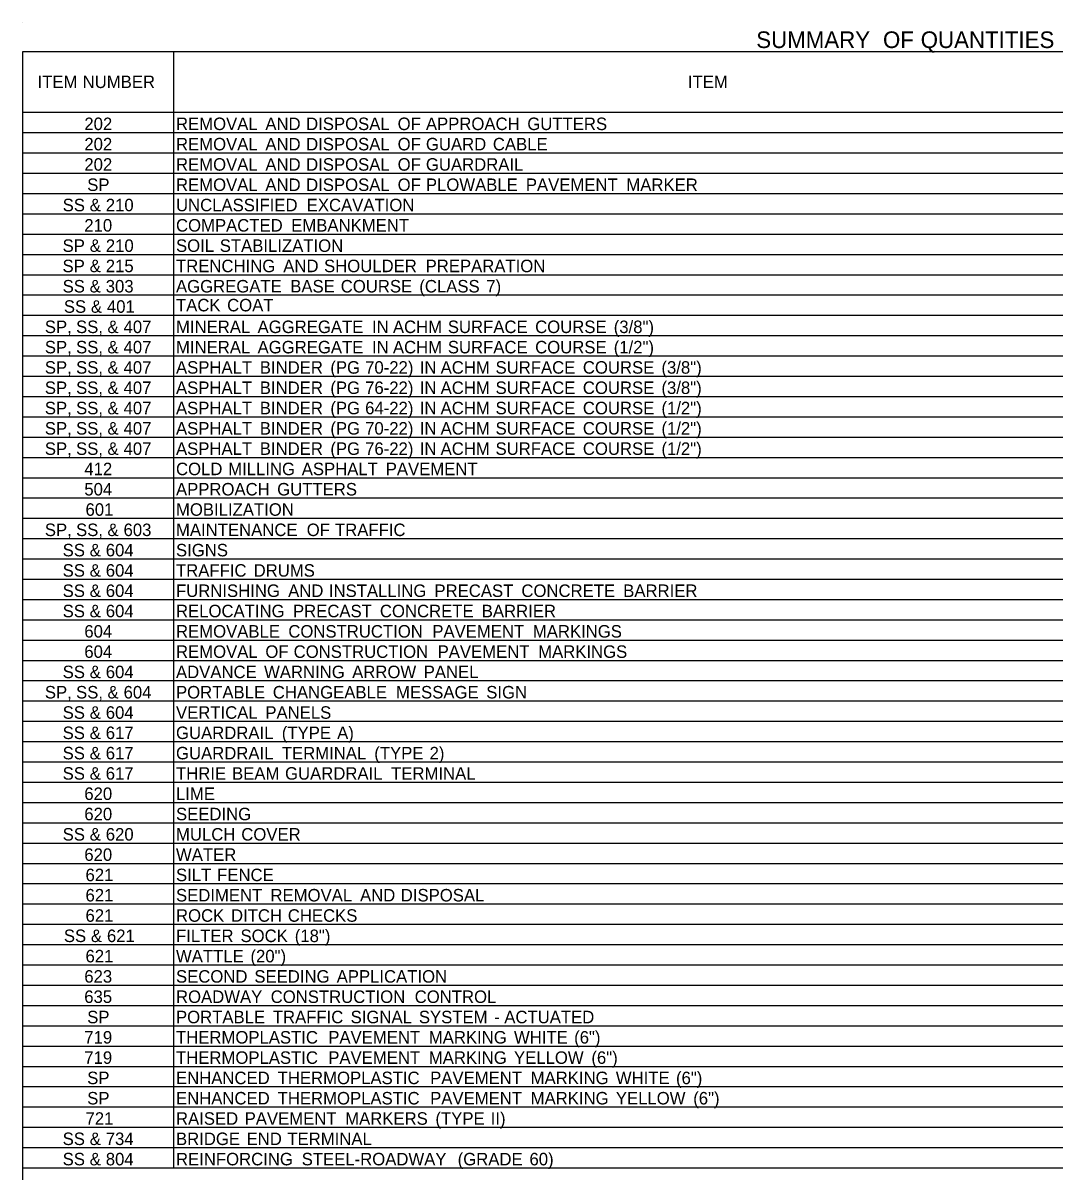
# Model space of a CAD drawing. Extents: x 540541 to 1930787, y -1948574 to 596640.
# Drawn here: x 548276 to 548771, y -1948161 to -1947610 of the extents above; entities that cross this region are included whole.
import ezdxf

# ---------------------------------------------------------------- set-up
doc = ezdxf.new("R2010")
doc.units = 0
doc.layers.add('Default', color=7, linetype='Continuous')
doc.layers.add('R_Border', color=7, linetype='Continuous')

msp = doc.modelspace()

# ---------------------------------------------------------------- linework, layer by layer
at = {"layer": 'Default'}
for p, q in [((548275.56, -1947623.57), (549254.46, -1947623.57)), ((548275.56, -1948315.82), (548275.56, -1947623.57)), ((548348.1, -1948159.82), (548348.1, -1947623.57)), ((548275.56, -1947652.82), (549254.46, -1947652.82)), ((548275.56, -1947652.82), (549254.46, -1947652.82)), ((548348.1, -1948159.82), (548348.1, -1947652.82)), ((548275.56, -1947662.57), (549254.46, -1947662.57)), ((548275.56, -1947672.32), (549254.46, -1947672.32)), ((548275.56, -1947682.07), (549254.46, -1947682.07)), ((548275.56, -1947691.82), (549254.46, -1947691.82)), ((548275.56, -1947701.57), (549254.46, -1947701.57)), ((548275.56, -1947711.32), (549254.46, -1947711.32)), ((548275.56, -1947721.07), (549254.46, -1947721.07)), ((548275.56, -1947730.82), (549254.46, -1947730.82)), ((548275.56, -1947740.57), (549254.46, -1947740.57)), ((548275.56, -1947750.32), (549254.46, -1947750.32)), ((548275.56, -1947760.07), (549254.46, -1947760.07)), ((548275.56, -1947769.82), (549254.46, -1947769.82)), ((548275.56, -1947779.57), (549254.46, -1947779.57)), ((548275.56, -1947789.32), (549254.46, -1947789.32)), ((548275.56, -1947799.07), (549254.46, -1947799.07)), ((548275.56, -1947808.82), (549254.46, -1947808.82)), ((548275.56, -1947818.57), (549254.46, -1947818.57)), ((548275.56, -1947828.32), (549254.46, -1947828.32)), ((548275.56, -1947838.07), (549254.46, -1947838.07)), ((548275.56, -1947847.82), (549254.46, -1947847.82)), ((548275.56, -1947857.57), (549254.46, -1947857.57)), ((548275.56, -1947867.32), (549254.46, -1947867.32)), ((548275.56, -1947877.07), (549254.46, -1947877.07)), ((548275.56, -1947886.82), (549254.46, -1947886.82)), ((548275.56, -1947896.57), (549254.46, -1947896.57)), ((548275.56, -1947906.32), (549254.46, -1947906.32)), ((548275.56, -1947916.07), (549254.46, -1947916.07)), ((548275.56, -1947925.82), (549254.46, -1947925.82)), ((548275.56, -1947935.57), (549254.46, -1947935.57)), ((548275.56, -1947945.32), (549254.46, -1947945.32)), ((548275.56, -1947955.07), (549254.46, -1947955.07)), ((548275.56, -1947964.82), (549254.46, -1947964.82)), ((548275.56, -1947974.57), (549254.46, -1947974.57)), ((548275.56, -1947984.32), (549254.46, -1947984.32)), ((548275.56, -1947994.07), (549254.46, -1947994.07)), ((548275.56, -1948003.82), (549254.46, -1948003.82)), ((548275.56, -1948013.57), (549254.46, -1948013.57)), ((548275.56, -1948023.32), (549254.46, -1948023.32)), ((548275.56, -1948033.07), (549254.46, -1948033.07)), ((548275.56, -1948042.82), (549254.46, -1948042.82)), ((548275.56, -1948052.57), (549254.46, -1948052.57)), ((548275.56, -1948062.32), (549254.46, -1948062.32)), ((548275.56, -1948072.07), (549254.46, -1948072.07)), ((548275.56, -1948081.82), (549254.46, -1948081.82)), ((548275.56, -1948091.57), (549254.46, -1948091.57)), ((548275.56, -1948101.32), (549254.46, -1948101.32)), ((548275.56, -1948111.07), (549254.46, -1948111.07)), ((548275.56, -1948120.82), (549254.46, -1948120.82)), ((548275.56, -1948130.57), (549254.46, -1948130.57)), ((548275.56, -1948140.32), (549254.46, -1948140.32)), ((548275.56, -1948150.07), (549254.46, -1948150.07)), ((548275.56, -1948159.82), (549254.46, -1948159.82)), ((548275.56, -1948159.82), (549254.46, -1948159.82))]:
    msp.add_line(p, q, dxfattribs=at)
at = {"layer": 'R_Border'}
msp.add_line((548275.56, -1947609.92), (548275.56, -1947609.92), dxfattribs=at)

# ---------------------------------------------------------------- texts
at = {"layer": 'Default'}
for s, height, p in [(' SUMMARY', 8, (548624.87, -1947621.97)), (' OF', 8, (548685.75, -1947621.97)), (' QUANTITIES', 8, (548703.86, -1947621.97)), ('ITEM', 6, (548282.58, -1947641.19)), (' NUMBER', 6, (548302, -1947641.19)), ('ITEM', 6, (548595.01, -1947641.19)), ('202', 6, (548305.06, -1947661.37)), ('REMOVAL', 6, (548349.08, -1947661.37)), (' AND', 6, (548389.78, -1947661.37)), (' DISPOSAL', 6, (548409.36, -1947661.37)), (' OF', 6, (548453.33, -1947661.37)), (' APPROACH', 6, (548466.91, -1947661.37)), (' GUTTERS', 6, (548515.62, -1947661.37)), ('202', 6, (548305.06, -1947671.12)), ('REMOVAL', 6, (548349.08, -1947671.12)), (' AND', 6, (548389.78, -1947671.12)), (' DISPOSAL', 6, (548409.36, -1947671.12)), (' OF', 6, (548453.33, -1947671.12)), (' GUARD', 6, (548466.91, -1947671.12)), (' CABLE', 6, (548499.07, -1947671.12)), ('202', 6, (548305.06, -1947680.87)), ('REMOVAL', 6, (548349.08, -1947680.87)), (' AND', 6, (548389.78, -1947680.87)), (' DISPOSAL', 6, (548409.36, -1947680.87)), (' OF', 6, (548453.33, -1947680.87)), (' GUARDRAIL', 6, (548466.91, -1947680.87)), ('SP', 6, (548306.42, -1947690.62)), ('REMOVAL', 6, (548349.08, -1947690.62)), (' AND', 6, (548389.78, -1947690.62)), (' DISPOSAL', 6, (548409.36, -1947690.62)), (' OF', 6, (548453.33, -1947690.62)), (' PLOWABLE', 6, (548466.91, -1947690.62)), (' PAVEMENT', 6, (548514.92, -1947690.62)), (' MARKER', 6, (548563.2, -1947690.62)), ('SS', 6, (548294.64, -1947700.37)), (' &', 6, (548305.39, -1947700.37)), (' 210', 6, (548313.12, -1947700.37)), ('UNCLASSIFIED', 6, (548349.08, -1947700.37)), (' EXCAVATION', 6, (548409.66, -1947700.37)), ('210', 6, (548305.04, -1947710.12)), ('COMPACTED', 6, (548349.08, -1947710.12)), (' EMBANKMENT', 6, (548402.2, -1947710.12)), ('SP', 6, (548294.6, -1947719.87)), (' &', 6, (548305.42, -1947719.87)), (' 210', 6, (548313.15, -1947719.87)), ('SOIL', 6, (548349.08, -1947719.87)), (' STABILIZATION', 6, (548367.88, -1947719.87)), ('SP', 6, (548294.57, -1947729.62)), (' &', 6, (548305.39, -1947729.62)), (' 215', 6, (548313.12, -1947729.62)), ('TRENCHING', 6, (548349.08, -1947729.62)), (' AND', 6, (548398.39, -1947729.62)), (' SHOULDER', 6, (548417.97, -1947729.62)), (' PREPARATION', 6, (548466.77, -1947729.62)), (' (CLASS', 6, (548463.74, -1947739.37)), (' 7)', 6, (548495.92, -1947739.37)), ('SS', 6, (548294.63, -1947739.37)), (' &', 6, (548305.38, -1947739.37)), (' 303', 6, (548313.1, -1947739.37)), ('AGGREGATE', 6, (548349.08, -1947739.37)), (' BASE', 6, (548401.74, -1947739.37)), (' COURSE', 6, (548425.99, -1947739.37)), ('SS', 6, (548295.21, -1947749.12)), (' &', 6, (548305.96, -1947749.12)), (' 401', 6, (548313.68, -1947749.12)), ('TACK', 6, (548349.08, -1947748.44)), (' COAT', 6, (548371.42, -1947748.44)), ('SP,', 6, (548286.07, -1947758.87)), (' SS,', 6, (548298.84, -1947758.87)), (' &', 6, (548313.93, -1947758.87)), (' 407', 6, (548321.66, -1947758.87)), ('MINERAL', 6, (548349.08, -1947758.87)), (' AGGREGATE', 6, (548386.04, -1947758.87)), (' IN', 6, (548441.04, -1947758.87)), (' ACHM', 6, (548451.06, -1947758.87)), (' SURFACE', 6, (548477.44, -1947758.87)), (' COURSE', 6, (548519.39, -1947758.87)), (' (3/8")', 6, (548557.14, -1947758.87)), ('SP,', 6, (548286.07, -1947768.62)), (' SS,', 6, (548298.84, -1947768.62)), (' &', 6, (548313.93, -1947768.62)), (' 407', 6, (548321.66, -1947768.62)), ('MINERAL', 6, (548349.08, -1947768.62)), (' AGGREGATE', 6, (548386.04, -1947768.62)), (' IN', 6, (548441.04, -1947768.62)), (' ACHM', 6, (548451.06, -1947768.62)), (' SURFACE', 6, (548477.44, -1947768.62)), (' COURSE', 6, (548519.39, -1947768.62)), (' (1/2")', 6, (548557.14, -1947768.62)), ('SP,', 6, (548286.07, -1947778.37)), (' SS,', 6, (548298.84, -1947778.37)), (' &', 6, (548313.93, -1947778.37)), (' 407', 6, (548321.66, -1947778.37)), ('ASPHALT', 6, (548349.08, -1947778.37)), (' BINDER', 6, (548387.11, -1947778.37)), (' (PG', 6, (548421.01, -1947778.37)), (' 70-22)', 6, (548437.71, -1947778.37)), (' IN', 6, (548463.96, -1947778.37)), (' ACHM', 6, (548473.98, -1947778.37)), (' SURFACE', 6, (548500.36, -1947778.37)), (' COURSE', 6, (548542.31, -1947778.37)), (' (3/8")', 6, (548580.06, -1947778.37)), ('SP,', 6, (548286.07, -1947788.12)), (' SS,', 6, (548298.84, -1947788.12)), (' &', 6, (548313.93, -1947788.12)), (' 407', 6, (548321.66, -1947788.12)), ('ASPHALT', 6, (548349.08, -1947788.12)), (' BINDER', 6, (548387.11, -1947788.12)), (' (PG', 6, (548421.01, -1947788.12)), (' 76-22)', 6, (548437.71, -1947788.12)), (' IN', 6, (548463.96, -1947788.12)), (' ACHM', 6, (548473.98, -1947788.12)), (' SURFACE', 6, (548500.36, -1947788.12)), (' COURSE', 6, (548542.31, -1947788.12)), (' (3/8")', 6, (548580.06, -1947788.12)), ('SP,', 6, (548286.07, -1947797.87)), (' SS,', 6, (548298.84, -1947797.87)), (' &', 6, (548313.93, -1947797.87)), (' 407', 6, (548321.66, -1947797.87)), ('ASPHALT', 6, (548349.08, -1947797.87)), (' BINDER', 6, (548387.11, -1947797.87)), (' (PG', 6, (548421.01, -1947797.87)), (' 64-22)', 6, (548437.71, -1947797.87)), (' IN', 6, (548463.96, -1947797.87)), (' ACHM', 6, (548473.98, -1947797.87)), (' SURFACE', 6, (548500.36, -1947797.87)), (' COURSE', 6, (548542.31, -1947797.87)), (' (1/2")', 6, (548580.06, -1947797.87)), ('SP,', 6, (548286.07, -1947807.62)), (' SS,', 6, (548298.84, -1947807.62)), (' &', 6, (548313.93, -1947807.62)), (' 407', 6, (548321.66, -1947807.62)), ('ASPHALT', 6, (548349.08, -1947807.62)), (' BINDER', 6, (548387.11, -1947807.62)), (' (PG', 6, (548421.01, -1947807.62)), (' 70-22)', 6, (548437.71, -1947807.62)), (' IN', 6, (548463.96, -1947807.62)), (' ACHM', 6, (548473.98, -1947807.62)), (' SURFACE', 6, (548500.36, -1947807.62)), (' COURSE', 6, (548542.31, -1947807.62)), (' (1/2")', 6, (548580.06, -1947807.62)), ('SP,', 6, (548286.07, -1947817.37)), (' SS,', 6, (548298.84, -1947817.37)), (' &', 6, (548313.93, -1947817.37)), (' 407', 6, (548321.66, -1947817.37)), ('ASPHALT', 6, (548349.08, -1947817.37)), (' BINDER', 6, (548387.11, -1947817.37)), (' (PG', 6, (548421.01, -1947817.37)), (' 76-22)', 6, (548437.71, -1947817.37)), (' IN', 6, (548463.96, -1947817.37)), (' ACHM', 6, (548473.98, -1947817.37)), (' SURFACE', 6, (548500.36, -1947817.37)), (' COURSE', 6, (548542.31, -1947817.37)), (' (1/2")', 6, (548580.06, -1947817.37)), ('412', 6, (548305.06, -1947827.12)), ('COLD', 6, (548349.08, -1947827.12)), (' MILLING', 6, (548371.92, -1947827.12)), (' ASPHALT', 6, (548407.26, -1947827.12)), (' PAVEMENT', 6, (548447.62, -1947827.12)), ('504', 6, (548305.04, -1947836.87)), ('APPROACH', 6, (548349.08, -1947836.87)), (' GUTTERS', 6, (548395.46, -1947836.87)), ('601', 6, (548305.61, -1947846.62)), ('MOBILIZATION', 6, (548349.08, -1947846.62)), ('SP,', 6, (548286.07, -1947856.37)), (' SS,', 6, (548298.84, -1947856.37)), (' &', 6, (548313.93, -1947856.37)), (' 603', 6, (548321.66, -1947856.37)), ('MAINTENANCE', 6, (548349.08, -1947856.37)), (' OF', 6, (548409.65, -1947856.37)), (' TRAFFIC', 6, (548423.24, -1947856.37)), ('SS', 6, (548294.64, -1947866.12)), (' 604', 6, (548313.12, -1947866.12)), ('SIGNS', 6, (548349.08, -1947866.12)), (' &', 6, (548305.39, -1947866.12)), ('SS', 6, (548294.64, -1947875.87)), (' &', 6, (548305.39, -1947875.87)), (' 604', 6, (548313.12, -1947875.87)), ('TRAFFIC', 6, (548349.08, -1947875.87)), (' DRUMS', 6, (548384.14, -1947875.87)), ('SS', 6, (548294.64, -1947885.62)), (' &', 6, (548305.39, -1947885.62)), (' 604', 6, (548313.12, -1947885.62)), ('FURNISHING', 6, (548349.08, -1947885.62)), (' AND', 6, (548400.72, -1947885.62)), (' INSTALLING', 6, (548420.3, -1947885.62)), (' PRECAST', 6, (548471.01, -1947885.62)), (' CONCRETE', 6, (548512.78, -1947885.62)), (' BARRIER', 6, (548561.7, -1947885.62)), ('SS', 6, (548294.64, -1947895.37)), (' &', 6, (548305.39, -1947895.37)), (' 604', 6, (548313.12, -1947895.37)), ('RELOCATING', 6, (548349.08, -1947895.37)), (' PRECAST', 6, (548403.05, -1947895.37)), (' CONCRETE', 6, (548444.81, -1947895.37)), (' BARRIER', 6, (548493.74, -1947895.37)), ('604', 6, (548305.04, -1947905.12)), ('REMOVABLE', 6, (548349.08, -1947905.12)), (' CONSTRUCTION', 6, (548400.81, -1947905.12)), (' PAVEMENT', 6, (548469.99, -1947905.12)), (' MARKINGS', 6, (548518.27, -1947905.12)), ('604', 6, (548305.04, -1947914.87)), ('REMOVAL', 6, (548349.08, -1947914.87)), (' OF', 6, (548389.78, -1947914.87)), (' CONSTRUCTION', 6, (548403.36, -1947914.87)), (' PAVEMENT', 6, (548472.54, -1947914.87)), (' MARKINGS', 6, (548520.83, -1947914.87)), ('SS', 6, (548294.64, -1947924.62)), (' &', 6, (548305.39, -1947924.62)), (' 604', 6, (548313.12, -1947924.62)), ('ADVANCE', 6, (548349.08, -1947924.62)), (' WARNING', 6, (548389.16, -1947924.62)), (' ARROW', 6, (548431.48, -1947924.62)), (' PANEL', 6, (548465.85, -1947924.62)), ('SP,', 6, (548286.08, -1947934.37)), (' SS,', 6, (548298.85, -1947934.37)), (' &', 6, (548313.95, -1947934.37)), (' 604', 6, (548321.68, -1947934.37)), ('PORTABLE', 6, (548349.08, -1947934.37)), (' CHANGEABLE', 6, (548393.36, -1947934.37)), (' MESSAGE', 6, (548452.55, -1947934.37)), (' SIGN', 6, (548495.9, -1947934.37)), ('SS', 6, (548294.64, -1947944.12)), (' &', 6, (548305.39, -1947944.12)), (' 604', 6, (548313.12, -1947944.12)), ('VERTICAL', 6, (548349.08, -1947944.12)), (' PANELS', 6, (548389.78, -1947944.12)), ('SS', 6, (548294.63, -1947953.87)), (' &', 6, (548305.38, -1947953.87)), (' 617', 6, (548313.1, -1947953.87)), ('GUARDRAIL', 6, (548349.08, -1947953.87)), (' (TYPE', 6, (548397.69, -1947953.87)), (' A)', 6, (548424.26, -1947953.87)), ('SS', 6, (548294.63, -1947963.62)), (' &', 6, (548305.38, -1947963.62)), (' 617', 6, (548313.1, -1947963.62)), ('GUARDRAIL', 6, (548349.08, -1947963.62)), (' TERMINAL', 6, (548397.69, -1947963.62)), (' (TYPE', 6, (548442.11, -1947963.62)), (' 2)', 6, (548468.68, -1947963.62)), ('SS', 6, (548294.63, -1947973.37)), (' &', 6, (548305.38, -1947973.37)), (' 617', 6, (548313.1, -1947973.37)), ('THRIE', 6, (548349.08, -1947973.37)), (' BEAM', 6, (548373.78, -1947973.37)), (' GUARDRAIL', 6, (548399.24, -1947973.37)), (' TERMINAL', 6, (548450.18, -1947973.37)), ('620', 6, (548305.04, -1947983.12)), ('LIME', 6, (548349.08, -1947983.12)), ('620', 6, (548305.04, -1947992.87)), ('SEEDING', 6, (548349.08, -1947992.87)), ('SS', 6, (548294.64, -1948002.62)), (' &', 6, (548305.39, -1948002.62)), (' 620', 6, (548313.12, -1948002.62)), ('MULCH', 6, (548349.08, -1948002.62)), (' COVER', 6, (548378.21, -1948002.62)), ('620', 6, (548305.04, -1948012.37)), ('WATER', 6, (548349.08, -1948012.37)), ('621', 6, (548305.61, -1948022.12)), ('SILT', 6, (548349.08, -1948022.12)), (' FENCE', 6, (548366.61, -1948022.12)), ('621', 6, (548305.61, -1948031.87)), ('SEDIMENT', 6, (548349.08, -1948031.87)), (' REMOVAL', 6, (548392.23, -1948031.87)), (' AND', 6, (548435.26, -1948031.87)), (' DISPOSAL', 6, (548454.84, -1948031.87)), ('621', 6, (548305.61, -1948041.62)), ('ROCK', 6, (548349.08, -1948041.62)), (' DITCH', 6, (548373.28, -1948041.62)), (' CHECKS', 6, (548400.55, -1948041.62)), ('SS', 6, (548295.21, -1948051.37)), (' &', 6, (548305.96, -1948051.37)), (' 621', 6, (548313.68, -1948051.37)), ('FILTER', 6, (548349.08, -1948051.37)), (' SOCK', 6, (548377.84, -1948051.37)), (' (18")', 6, (548403.91, -1948051.37)), ('621', 6, (548305.61, -1948061.12)), ('WATTLE', 6, (548349.08, -1948061.12)), (' (20")', 6, (548382.63, -1948061.12)), ('623', 6, (548305.03, -1948070.87)), ('SECOND', 6, (548349.08, -1948070.87)), (' SEEDING', 6, (548384.5, -1948070.87)), (' APPLICATION', 6, (548424.04, -1948070.87)), ('635', 6, (548305.01, -1948080.62)), ('ROADWAY', 6, (548349.08, -1948080.62)), (' CONSTRUCTION', 6, (548392.33, -1948080.62)), (' CONTROL', 6, (548461.51, -1948080.62)), ('SP', 6, (548306.42, -1948090.37)), ('PORTABLE', 6, (548349.08, -1948090.37)), (' TRAFFIC', 6, (548393.36, -1948090.37)), (' SIGNAL', 6, (548430.75, -1948090.37)), (' SYSTEM', 6, (548463.53, -1948090.37)), (' ACTUATED', 6, (548504.56, -1948090.37)), (' -', 6, (548499.7, -1948090.37)), ('719', 6, (548305.03, -1948100.12)), ('THERMOPLASTIC', 6, (548349.08, -1948100.12)), (' PAVEMENT', 6, (548420.01, -1948100.12)), (' MARKING', 6, (548468.3, -1948100.12)), (' WHITE', 6, (548509.23, -1948100.12)), (' (6")', 6, (548538.12, -1948100.12)), ('719', 6, (548305.03, -1948109.87)), ('THERMOPLASTIC', 6, (548349.08, -1948109.87)), (' PAVEMENT', 6, (548420.01, -1948109.87)), (' MARKING', 6, (548468.3, -1948109.87)), (' YELLOW', 6, (548509.23, -1948109.87)), (' (6")', 6, (548546.4, -1948109.87)), ('SP', 6, (548306.42, -1948119.62)), ('ENHANCED', 6, (548349.08, -1948119.62)), (' THERMOPLASTIC', 6, (548395.68, -1948119.62)), (' PAVEMENT', 6, (548468.95, -1948119.62)), (' MARKING', 6, (548517.23, -1948119.62)), (' WHITE', 6, (548558.16, -1948119.62)), (' (6")', 6, (548587.05, -1948119.62)), ('SP', 6, (548306.42, -1948129.37)), ('ENHANCED', 6, (548349.08, -1948129.37)), (' THERMOPLASTIC', 6, (548395.68, -1948129.37)), (' PAVEMENT', 6, (548468.95, -1948129.37)), (' MARKING', 6, (548517.23, -1948129.37)), (' YELLOW', 6, (548558.16, -1948129.37)), (' (6")', 6, (548595.33, -1948129.37)), ('721', 6, (548305.61, -1948139.12)), ('RAISED', 6, (548349.08, -1948139.12)), (' PAVEMENT', 6, (548379.84, -1948139.12)), (' MARKERS', 6, (548428.13, -1948139.12)), (' (TYPE', 6, (548471.48, -1948139.12)), (' II)', 6, (548498.05, -1948139.12)), ('SS', 6, (548294.64, -1948148.87)), (' &', 6, (548305.39, -1948148.87)), (' 734', 6, (548313.12, -1948148.87)), ('BRIDGE', 6, (548349.08, -1948148.87)), (' END', 6, (548380.77, -1948148.87)), (' TERMINAL', 6, (548400.35, -1948148.87)), (' (GRADE', 6, (548482.17, -1948158.62)), (' 60)', 6, (548516.66, -1948158.62)), ('SS', 6, (548294.64, -1948158.62)), (' &', 6, (548305.39, -1948158.62)), (' 804', 6, (548313.12, -1948158.62)), ('REINFORCING', 6, (548349.08, -1948158.62)), (' STEEL-ROADWAY', 6, (548407.24, -1948158.62))]:
    msp.add_text(s, height=height, dxfattribs=at).set_placement(p)

doc.saveas('drawing.dxf')
